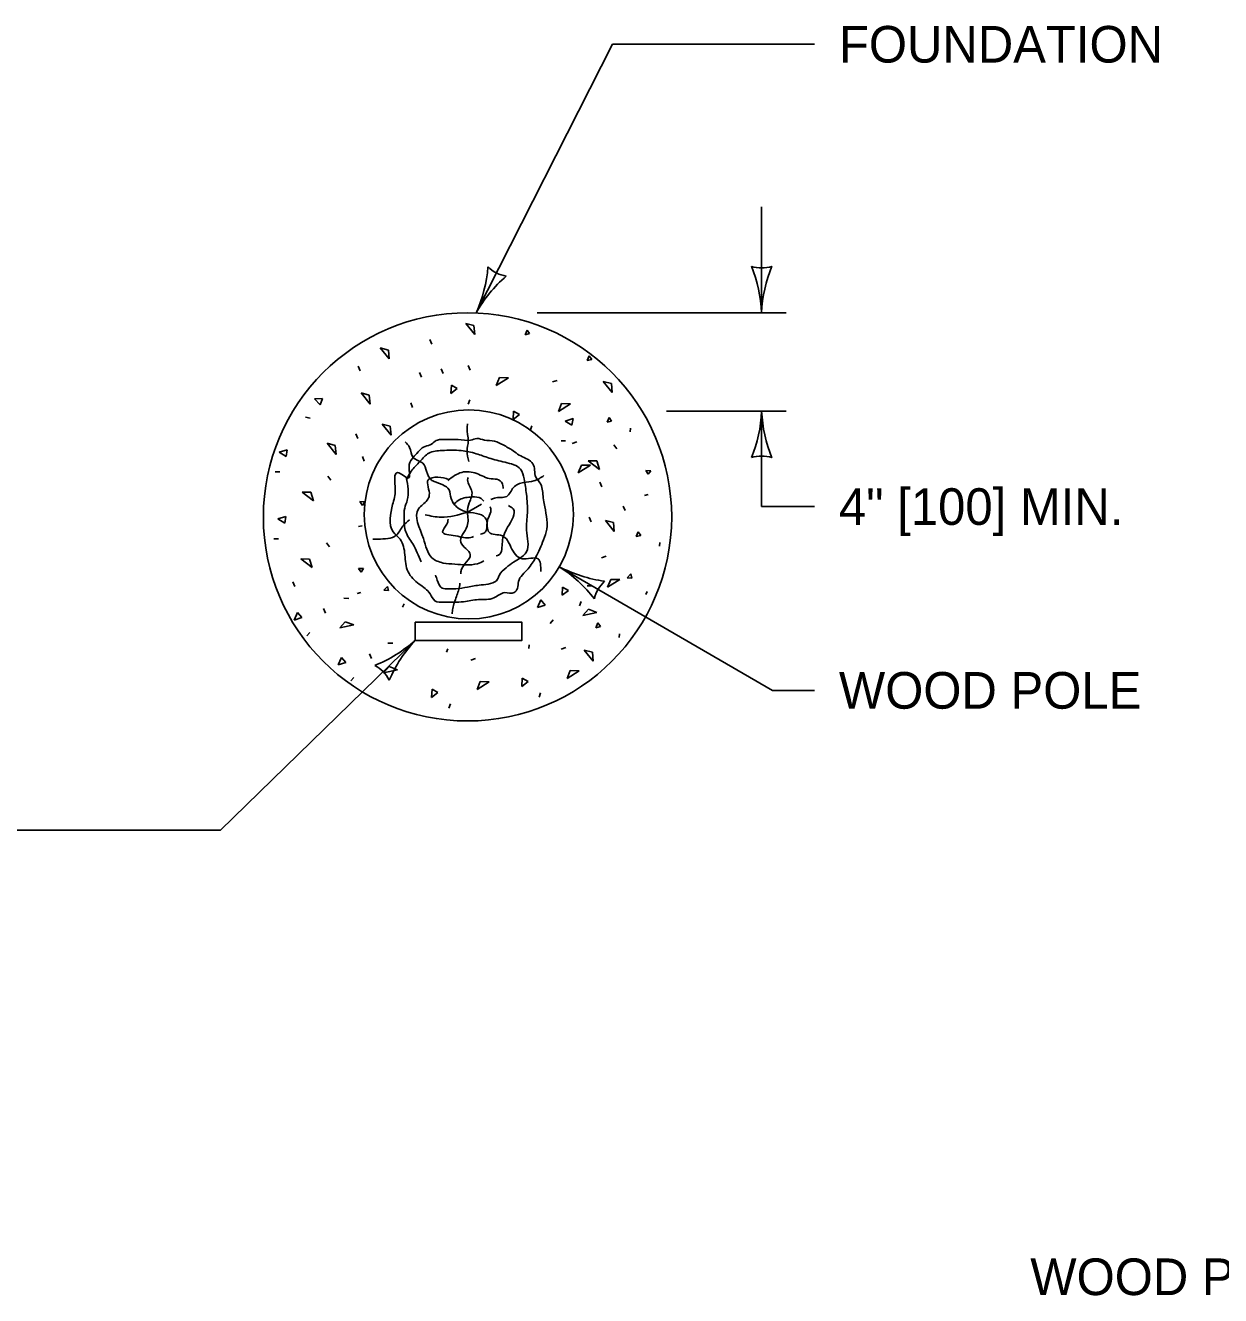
# Model space of a CAD drawing. Extents: x 49991.4 to 50021, y 49987.6 to 50011.4.
# Drawn here: x 50006.887 to 50008.843, y 49993.794 to 49995.873 of the extents above; entities that cross this region are included whole.
import ezdxf

# ---------------------------------------------------------------- set-up
doc = ezdxf.new("R2010")
doc.units = 0
for name, color, linetype in [('Level 1', 7, 'Continuous'), ('Level 2', 7, 'Continuous'), ('Level 3', 7, 'Continuous')]:
    doc.layers.add(name, color=color, linetype=linetype)

msp = doc.modelspace()

# ---------------------------------------------------------------- linework, layer by layer
at = {"layer": 'Level 1'}
for p, q in [((50007.6207, 49995.382), (50007.6074, 49995.3857)), ((50007.6074, 49995.3857), (50007.622, 49995.3674)), ((50007.622, 49995.3674), (50007.6207, 49995.382)), ((50007.7044, 49995.3671), (50007.7077, 49995.3748)), ((50007.7117, 49995.3689), (50007.7044, 49995.3671)), ((50007.7077, 49995.3748), (50007.7117, 49995.3689)), ((50007.4809, 49995.342), (50007.4676, 49995.3457)), ((50007.4676, 49995.3457), (50007.4822, 49995.3274)), ((50007.5519, 49995.3517), (50007.5487, 49995.3592)), ((50007.4822, 49995.3274), (50007.4809, 49995.342)), ((50007.8062, 49995.3247), (50007.8095, 49995.3324)), ((50007.8135, 49995.3265), (50007.8062, 49995.3247)), ((50007.8095, 49995.3324), (50007.8135, 49995.3265)), ((50007.4348, 49995.3079), (50007.4316, 49995.3154)), ((50007.5348, 49995.2978), (50007.5316, 49995.3053)), ((50007.5705, 49995.3038), (50007.5673, 49995.3113)), ((50007.6146, 49995.3091), (50007.6114, 49995.3166)), ((50007.5831, 49995.2708), (50007.5839, 49995.2844)), ((50007.5839, 49995.2844), (50007.5934, 49995.2789)), ((50007.6625, 49995.2969), (50007.6574, 49995.284)), ((50007.6574, 49995.284), (50007.6772, 49995.2965)), ((50007.6772, 49995.2965), (50007.6625, 49995.2969)), ((50007.7569, 49995.2923), (50007.7492, 49995.2898)), ((50007.8457, 49995.2871), (50007.8324, 49995.2908)), ((50007.8324, 49995.2908), (50007.847, 49995.2725)), ((50007.847, 49995.2725), (50007.8457, 49995.2871)), ((50007.3597, 49995.262), (50007.3731, 49995.2627)), ((50007.3731, 49995.2627), (50007.3689, 49995.2526)), ((50007.4495, 49995.2682), (50007.4362, 49995.2719)), ((50007.4362, 49995.2719), (50007.4508, 49995.2536)), ((50007.4508, 49995.2536), (50007.4495, 49995.2682)), ((50007.5934, 49995.2789), (50007.5831, 49995.2708)), ((50007.3689, 49995.2526), (50007.3597, 49995.262)), ((50007.5205, 49995.2481), (50007.5173, 49995.2556)), ((50007.614, 49995.2605), (50007.6114, 49995.2536)), ((50007.6849, 49995.2284), (50007.6857, 49995.242)), ((50007.6857, 49995.242), (50007.6952, 49995.2365)), ((50007.7643, 49995.2545), (50007.7592, 49995.2416)), ((50007.7592, 49995.2416), (50007.779, 49995.2541)), ((50007.779, 49995.2541), (50007.7643, 49995.2545)), ((50007.3526, 49995.2303), (50007.3454, 49995.232)), ((50007.4838, 49995.2172), (50007.4705, 49995.2209)), ((50007.4705, 49995.2209), (50007.4851, 49995.2026)), ((50007.6952, 49995.2365), (50007.6849, 49995.2284)), ((50007.77, 49995.2258), (50007.7831, 49995.2299)), ((50007.781, 49995.2191), (50007.77, 49995.2258)), ((50007.7831, 49995.2299), (50007.781, 49995.2191)), ((50007.8386, 49995.2239), (50007.8419, 49995.2316)), ((50007.8459, 49995.2257), (50007.8386, 49995.2239)), ((50007.8419, 49995.2316), (50007.8459, 49995.2257)), ((50007.4307, 49995.1971), (50007.4275, 49995.2046)), ((50007.4851, 49995.2026), (50007.4838, 49995.2172)), ((50007.7158, 49995.2181), (50007.7132, 49995.2112)), ((50007.8764, 49995.2081), (50007.8771, 49995.2139)), ((50007.3939, 49995.1858), (50007.3806, 49995.1895)), ((50007.3806, 49995.1895), (50007.3952, 49995.1712)), ((50007.3952, 49995.1712), (50007.3939, 49995.1858)), ((50007.7708, 49995.1934), (50007.7635, 49995.1935)), ((50007.7893, 49995.1915), (50007.7816, 49995.189)), ((50007.8547, 49995.1802), (50007.8496, 49995.1866)), ((50007.3021, 49995.1749), (50007.315, 49995.1788)), ((50007.3133, 49995.168), (50007.3021, 49995.1749)), ((50007.315, 49995.1788), (50007.3133, 49995.168)), ((50007.4414, 49995.1603), (50007.4382, 49995.1678)), ((50007.8217, 49995.1604), (50007.8078, 49995.1606)), ((50007.8078, 49995.1606), (50007.8263, 49995.1463)), ((50007.8263, 49995.1463), (50007.8217, 49995.1604)), ((50007.3029, 49995.1424), (50007.2955, 49995.1424)), ((50007.7967, 49995.1537), (50007.7916, 49995.1408)), ((50007.7916, 49995.1408), (50007.8114, 49995.1533)), ((50007.8114, 49995.1533), (50007.7967, 49995.1537)), ((50007.902, 49995.145), (50007.9104, 49995.1443)), ((50007.9061, 49995.1388), (50007.902, 49995.145)), ((50007.9104, 49995.1443), (50007.9061, 49995.1388)), ((50007.3867, 49995.1291), (50007.3818, 49995.1356)), ((50007.83, 49995.1182), (50007.8268, 49995.1257)), ((50007.3537, 49995.1092), (50007.3399, 49995.1096)), ((50007.3399, 49995.1096), (50007.3585, 49995.0954)), ((50007.3585, 49995.0954), (50007.3537, 49995.1092)), ((50007.9, 49995.1041), (50007.9057, 49995.1055)), ((50007.434, 49995.0939), (50007.4423, 49995.0935)), ((50007.4383, 49995.0877), (50007.434, 49995.0939)), ((50007.4423, 49995.0935), (50007.4383, 49995.0877)), ((50007.6096, 49995.0763), (50007.6332, 49995.0895)), ((50007.8681, 49995.0791), (50007.8649, 49995.0866)), ((50007.2999, 49995.0656), (50007.3128, 49995.0695)), ((50007.3111, 49995.0587), (50007.2999, 49995.0656)), ((50007.3128, 49995.0695), (50007.3111, 49995.0587)), ((50007.8128, 49995.0607), (50007.8096, 49995.0682)), ((50007.8492, 49995.0595), (50007.8359, 49995.0632)), ((50007.8359, 49995.0632), (50007.8505, 49995.0449)), ((50007.8505, 49995.0449), (50007.8492, 49995.0595)), ((50007.432, 49995.053), (50007.4378, 49995.0543)), ((50007.8865, 49995.0368), (50007.8898, 49995.0445)), ((50007.8938, 49995.0386), (50007.8865, 49995.0368)), ((50007.8898, 49995.0445), (50007.8938, 49995.0386)), ((50007.3007, 49995.0331), (50007.2933, 49995.0331)), ((50007.3845, 49995.0198), (50007.3796, 49995.0263)), ((50007.9243, 49995.021), (50007.925, 49995.0268)), ((50007.3515, 49994.9999), (50007.3377, 49995.0003)), ((50007.3377, 49995.0003), (50007.3563, 49994.9861)), ((50007.3563, 49994.9861), (50007.3515, 49994.9999)), ((50007.8372, 49995.0044), (50007.8295, 49995.0019)), ((50007.4318, 49994.9846), (50007.4401, 49994.9842)), ((50007.4361, 49994.9784), (50007.4318, 49994.9846)), ((50007.4401, 49994.9842), (50007.4361, 49994.9784)), ((50007.8717, 49994.9693), (50007.8775, 49994.9755)), ((50007.8775, 49994.9755), (50007.8792, 49994.9686)), ((50007.3277, 49994.9551), (50007.3245, 49994.9626)), ((50007.4736, 49994.949), (50007.4794, 49994.9551)), ((50007.4794, 49994.9551), (50007.4811, 49994.9482)), ((50007.7652, 49994.9405), (50007.766, 49994.9541)), ((50007.766, 49994.9541), (50007.7755, 49994.9486)), ((50007.8143, 49994.9558), (50007.8062, 49994.9561)), ((50007.8446, 49994.9666), (50007.8395, 49994.9537)), ((50007.8395, 49994.9537), (50007.8593, 49994.9662)), ((50007.8593, 49994.9662), (50007.8446, 49994.9666)), ((50007.8792, 49994.9686), (50007.8717, 49994.9693)), ((50007.4162, 49994.9354), (50007.4081, 49994.9357)), ((50007.4298, 49994.9437), (50007.4356, 49994.945)), ((50007.4811, 49994.9482), (50007.4736, 49994.949)), ((50007.7248, 49994.9204), (50007.7301, 49994.9329)), ((50007.7301, 49994.9329), (50007.7372, 49994.9245)), ((50007.7755, 49994.9486), (50007.7652, 49994.9405)), ((50007.7961, 49994.9302), (50007.7935, 49994.9233)), ((50007.9019, 49994.9416), (50007.9045, 49994.9468)), ((50007.3267, 49994.9), (50007.3321, 49994.9124)), ((50007.3321, 49994.9124), (50007.3392, 49994.9041)), ((50007.3777, 49994.9113), (50007.3745, 49994.9188)), ((50007.5038, 49994.9211), (50007.5064, 49994.9264)), ((50007.7372, 49994.9245), (50007.7248, 49994.9204)), ((50007.8083, 49994.9178), (50007.7992, 49994.9074)), ((50007.7992, 49994.9074), (50007.822, 49994.9123)), ((50007.822, 49994.9123), (50007.8083, 49994.9178)), ((50007.3392, 49994.9041), (50007.3267, 49994.9)), ((50007.4103, 49994.8973), (50007.4011, 49994.887)), ((50007.4011, 49994.887), (50007.424, 49994.892)), ((50007.424, 49994.892), (50007.4103, 49994.8973)), ((50007.7503, 49994.9002), (50007.7455, 49994.8945)), ((50007.8204, 49994.8875), (50007.8237, 49994.8952)), ((50007.8277, 49994.8893), (50007.8204, 49994.8875)), ((50007.8237, 49994.8952), (50007.8277, 49994.8893)), ((50007.3523, 49994.8797), (50007.3474, 49994.8741)), ((50007.8582, 49994.8717), (50007.8589, 49994.8775)), ((50007.4881, 49994.8619), (50007.48, 49994.8622)), ((50007.5757, 49994.8476), (50007.5783, 49994.8529)), ((50007.7107, 49994.8537), (50007.7114, 49994.8595)), ((50007.7711, 49994.8551), (50007.7634, 49994.8526)), ((50007.8147, 49994.8472), (50007.8014, 49994.8509)), ((50007.8014, 49994.8509), (50007.816, 49994.8326)), ((50007.816, 49994.8326), (50007.8147, 49994.8472)), ((50007.3986, 49994.8265), (50007.404, 49994.8389)), ((50007.4111, 49994.8306), (50007.3986, 49994.8265)), ((50007.404, 49994.8389), (50007.4111, 49994.8306)), ((50007.4533, 49994.8371), (50007.4501, 49994.8446)), ((50007.6236, 49994.8371), (50007.6159, 49994.8346)), ((50007.4242, 49994.8062), (50007.4193, 49994.8006)), ((50007.4822, 49994.8238), (50007.473, 49994.8135)), ((50007.473, 49994.8135), (50007.4959, 49994.8185)), ((50007.4959, 49994.8185), (50007.4822, 49994.8238)), ((50007.7785, 49994.8173), (50007.7734, 49994.8044)), ((50007.7734, 49994.8044), (50007.7932, 49994.8169)), ((50007.7932, 49994.8169), (50007.7785, 49994.8173)), ((50007.5516, 49994.7732), (50007.5524, 49994.7868)), ((50007.5524, 49994.7868), (50007.5619, 49994.7813)), ((50007.631, 49994.7993), (50007.6259, 49994.7864)), ((50007.6259, 49994.7864), (50007.6457, 49994.7989)), ((50007.6457, 49994.7989), (50007.631, 49994.7993)), ((50007.6991, 49994.7912), (50007.6999, 49994.8048)), ((50007.7094, 49994.7993), (50007.6991, 49994.7912)), ((50007.6999, 49994.8048), (50007.7094, 49994.7993)), ((50007.5619, 49994.7813), (50007.5516, 49994.7732)), ((50007.73, 49994.7809), (50007.7274, 49994.774)), ((50007.5825, 49994.7629), (50007.5799, 49994.756))]:
    msp.add_line(p, q, dxfattribs=at)
msp.add_lwpolyline([(50007.5248, 49994.8964), (50007.6994, 49994.8964), (50007.6994, 49994.8668), (50007.5248, 49994.8668)], close=True, dxfattribs=at)
for centre, radius in [((50007.6103, 49995.0689), 0.3341), ((50007.6124, 49995.0729), 0.1711)]:
    msp.add_circle(centre, radius, dxfattribs=at)
for points in [[(50007.6125, 49995.1598), (50007.6096, 49995.1767), (50007.6114, 49995.1932), (50007.6096, 49995.2142), (50007.6105, 49995.2211)], [(50007.5208, 49995.1657), (50007.5297, 49995.1754), (50007.5383, 49995.1833), (50007.5489, 49995.1867), (50007.5576, 49995.1929), (50007.5646, 49995.1954), (50007.5794, 49995.1954), (50007.5951, 49995.1954), (50007.6151, 49995.1945), (50007.6257, 49995.1972), (50007.6379, 49995.1945), (50007.6545, 49995.1929), (50007.6685, 49995.1867), (50007.685, 49995.1771), (50007.6946, 49995.1701), (50007.7157, 49995.1579), (50007.7199, 49995.1484), (50007.7209, 49995.1369), (50007.7288, 49995.1247), (50007.734, 49995.1029), (50007.7357, 49995.0907), (50007.74, 49995.0488), (50007.7347, 49995.0313), (50007.7218, 49995.0025), (50007.7095, 49994.9841), (50007.6938, 49994.9631), (50007.6921, 49994.9519), (50007.6868, 49994.9449), (50007.6711, 49994.9449), (50007.6536, 49994.9362), (50007.6283, 49994.9335), (50007.6038, 49994.93), (50007.5725, 49994.9292), (50007.5568, 49994.9317), (50007.5489, 49994.943), (50007.5314, 49994.9588), (50007.513, 49994.9789), (50007.5078, 49995.0069), (50007.4999, 49995.0322), (50007.4886, 49995.0444), (50007.4878, 49995.089), (50007.492, 49995.1142), (50007.4956, 49995.1413), (50007.5139, 49995.1326), (50007.5148, 49995.1544), (50007.5218, 49995.1667)], [(50007.5084, 49995.1915), (50007.5154, 49995.1827), (50007.5215, 49995.1662), (50007.5372, 49995.1566), (50007.5434, 49995.1435), (50007.552, 49995.1287), (50007.5556, 49995.1269), (50007.58, 49995.113), (50007.5835, 49995.0989), (50007.5966, 49995.0823), (50007.6096, 49995.0763)], [(50007.5102, 49995.1295), (50007.518, 49995.1435), (50007.5328, 49995.1599), (50007.5468, 49995.1731), (50007.5687, 49995.1775), (50007.6, 49995.1775), (50007.6245, 49995.1723), (50007.6455, 49995.1652), (50007.6717, 49995.1583), (50007.6971, 49995.1469), (50007.7031, 49995.1312), (50007.7067, 49995.1059), (50007.7084, 49995.0753), (50007.7067, 49995.0474), (50007.7067, 49995.0115), (50007.6961, 49995.0011), (50007.6856, 49994.995), (50007.6734, 49994.9855), (50007.6621, 49994.9732), (50007.6595, 49994.9671), (50007.6324, 49994.9575), (50007.6105, 49994.9539), (50007.5914, 49994.9513), (50007.5792, 49994.9513), (50007.5687, 49994.9523), (50007.5608, 49994.9654), (50007.5579, 49994.9733)], [(50007.5783, 49995.1287), (50007.601, 49995.1418), (50007.6253, 49995.1399), (50007.649, 49995.1312), (50007.6612, 49995.1295), (50007.6682, 49995.1199), (50007.6685, 49995.1156)], [(50007.5342, 49994.9952), (50007.5207, 49995.0247), (50007.5092, 49995.0447), (50007.5066, 49995.0667), (50007.5075, 49995.0832), (50007.5118, 49995.0963), (50007.5102, 49995.133)], [(50007.6372, 49994.9967), (50007.6264, 49994.9923), (50007.5896, 49994.9915), (50007.5704, 49994.9934), (50007.552, 49995.002), (50007.5381, 49995.0335), (50007.5303, 49995.0823), (50007.5372, 49995.0893), (50007.5478, 49995.1042), (50007.546, 49995.1295), (50007.5616, 49995.1339), (50007.5792, 49995.1303)], [(50007.6096, 49995.0763), (50007.6132, 49995.092), (50007.6176, 49995.1102), (50007.6105, 49995.1295), (50007.6112, 49995.1335)], [(50007.6485, 49995.0971), (50007.6542, 49995.0998), (50007.6744, 49995.1024), (50007.6856, 49995.1172), (50007.7023, 49995.1251), (50007.7188, 49995.1277), (50007.7354, 49995.1365)], [(50007.637, 49995.0946), (50007.6324, 49995.0989), (50007.6176, 49995.1015), (50007.5975, 49995.0972), (50007.5888, 49995.091)], [(50007.6096, 49995.0763), (50007.5669, 49995.0683), (50007.5408, 49995.0724)], [(50007.6096, 49995.0763), (50007.6096, 49995.0535), (50007.5992, 49995.0273), (50007.6148, 49995.0072), (50007.6, 49994.9819), (50007.5995, 49994.9759)], [(50007.6096, 49995.0763), (50007.6411, 49995.064), (50007.6455, 49995.0439), (50007.6673, 49995.0378), (50007.6813, 49995.0195), (50007.6996, 49995.0003), (50007.7257, 49995.0003), (50007.7302, 49994.9793)], [(50007.6315, 49995.0406), (50007.6385, 49995.0431), (50007.6428, 49995.0623), (50007.6472, 49995.0849), (50007.6468, 49995.0854)], [(50007.6773, 49995.0873), (50007.6848, 49995.0823), (50007.676, 49995.0518), (50007.6673, 49995.0282), (50007.6612, 49995.0063), (50007.6573, 49995.0049)], [(50007.5156, 49995.0639), (50007.5049, 49995.0543), (50007.4936, 49995.0387), (50007.4639, 49995.0325), (50007.4555, 49995.0322)], [(50007.5787, 49995.065), (50007.5765, 49995.057), (50007.5695, 49995.0447), (50007.5904, 49995.0378), (50007.6158, 49995.0352), (50007.62, 49995.0367)], [(50007.5978, 49994.9603), (50007.5975, 49994.9575), (50007.5922, 49994.9383), (50007.5861, 49994.9191), (50007.585, 49994.9104)]]:
    msp.add_spline(points, degree=3, dxfattribs=at)
at = {"layer": 'Level 3'}
for p, q in [((50007.6244, 49995.4027), (50007.8474, 49995.8426)), ((50007.8474, 49995.8426), (50008.1781, 49995.8426)), ((50008.0916, 49995.403), (50008.0916, 49995.5764)), ((50007.7244, 49995.403), (50008.1316, 49995.403)), ((50007.9362, 49995.2419), (50008.1316, 49995.2419)), ((50008.0916, 49995.0858), (50008.0916, 49995.2419)), ((50008.0916, 49995.0858), (50008.1781, 49995.0858)), ((50007.7604, 49994.9872), (50008.1096, 49994.7849)), ((50007.5248, 49994.8668), (50007.2058, 49994.5559)), ((50008.1096, 49994.7849), (50008.1781, 49994.7849)), ((50006.5931, 49994.5559), (50007.2058, 49994.5559))]:
    msp.add_line(p, q, dxfattribs=at)
for centre, radius, start, end in [((50007.4115, 49995.4977), 0.2331, 335.9408, 355.1907), ((50007.6824, 49995.5171), 0.0548, 225.2523, 260.9747), ((50008.0916, 49995.5312), 0.0548, 252.1388, 287.8612), ((50007.8589, 49995.3915), 0.233, 2.8273, 22.0772), ((50008.3137, 49995.3939), 0.2223, 157.456, 177.6395), ((50007.8184, 49995.2941), 0.2224, 130.5695, 150.753), ((50007.8695, 49995.2511), 0.2223, 337.456, 357.6395), ((50008.3243, 49995.2534), 0.233, 182.8273, 202.0772), ((50008.0916, 49995.1137), 0.0548, 72.1388, 107.8612), ((50007.6412, 49994.7996), 0.2223, 37.372, 57.5555), ((50007.8671, 49995.1943), 0.233, 242.7433, 261.9931), ((50007.8714, 49994.9229), 0.0548, 132.0548, 167.7771), ((50007.3763, 49995.0323), 0.2223, 291.719, 311.9025), ((50007.6955, 49994.7082), 0.233, 137.0903, 156.3401), ((50007.433, 49994.7773), 0.0548, 26.4018, 62.1242)]:
    msp.add_arc(centre, radius, start, end, dxfattribs=at)

# ---------------------------------------------------------------- texts
at = {"layer": 'Level 2'}
for s, p in [('FOUNDATION', (50008.2181, 49995.8126)), ('4" [100] MIN.', (50008.2181, 49995.0558)), ('WOOD POLE', (50008.2181, 49994.7549)), ('WOOD POLE', (50008.5313, 49993.7949))]:
    msp.add_text(s, height=0.06, dxfattribs=at).set_placement(p)

doc.saveas('drawing.dxf')
